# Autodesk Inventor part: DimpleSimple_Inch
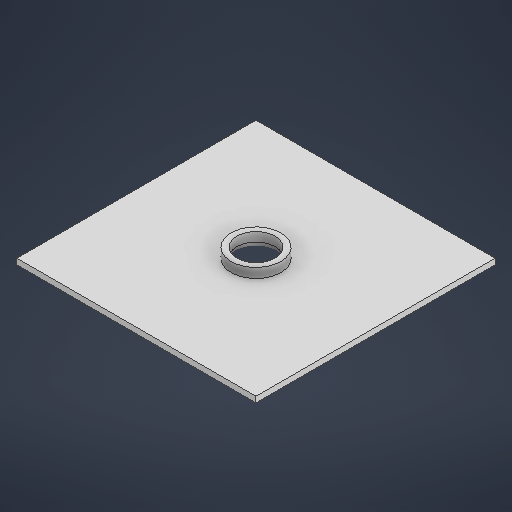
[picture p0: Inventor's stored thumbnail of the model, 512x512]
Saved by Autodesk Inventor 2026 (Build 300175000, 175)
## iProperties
Created: 2025-04
Part Number: DimpleSimple_Inch
Material: Generic
Document SubType Name: Sheet Metal
Designer: Autodesk, Inc
Density: 1 g/cm^3
Sheet Metal Rule: Default
Appearance: Default
Author: Autodesk, Inc
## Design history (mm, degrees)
node "Face1"
  sketch "Sketch1"
    geometry: L1 (-63.5, 63.5)-(63.5, 63.5); L2 (63.5, 63.5)-(63.5, -63.5); L3 (63.5, -63.5)-(-63.5, -63.5); L4 (-63.5, -63.5)-(-63.5, 63.5); L5 (-63.5, 63.5)-(63.5, -63.5); L6 (63.5, 63.5)-(-63.5, -63.5); 1 further point
    constraints: 12 end point, 2 midpoint, 2 parallel, 2 perpendicular, 1 horizontal
    dimensions: "d0" = 127 distance of L1.end L2.end
sketch "Sketch2"
  geometry: C1 r 13.208 at (0, 0); C2 r 10.16 at (0, 0); 2 further points
  constraints: 3 coincident, 2 centre point
  dimensions: "diameter" = 20.32 diameter of C2; "diameterB" = 26.416 diameter of C1 (= diameter + 2 x Thickness)
extrude "Extrusion1" join sketch "Sketch2" distance "d4" = 8.128 (= Thickness + height); taper "d5" = 0 deg
extrude "Extrusion2" cut sketch "Sketch2" distance "d6" = 8.128 (= Thickness + height); taper "d7" = 0 deg
fillet "Fillet1" dims "d8" = 3.302 (= fillet_radius)
body "Solid1"
face "Plate1" dims "d1" = 3.048 (= Thickness)
other parameters: "Thickness" = 3.048, "BendRadius" = 3.048 (= Thickness), "BendReliefWidth" = 3.048 (= Thickness), "BendReliefDepth" = 1.524 (= 0.5 x Thickness), "CornerReliefSize" = 12.192 (= 4 x Thickness), "SeamGap" = 0.00508, "MinimumRemnant" = 6.096 (= 2 x Thickness), "TransitionRadius" = 3.048 (= BendRadius), "JacobiRadiusSize" = 3.048 (= BendRadius), "GapSize" = 3.048 (= Thickness), "height" = 5.08 [user parameter; used in 2 equation terms], "fillet_radius" = 3.302 [user parameter; used in 1 equation term]
